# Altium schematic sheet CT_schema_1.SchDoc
size 540 x 499 mm
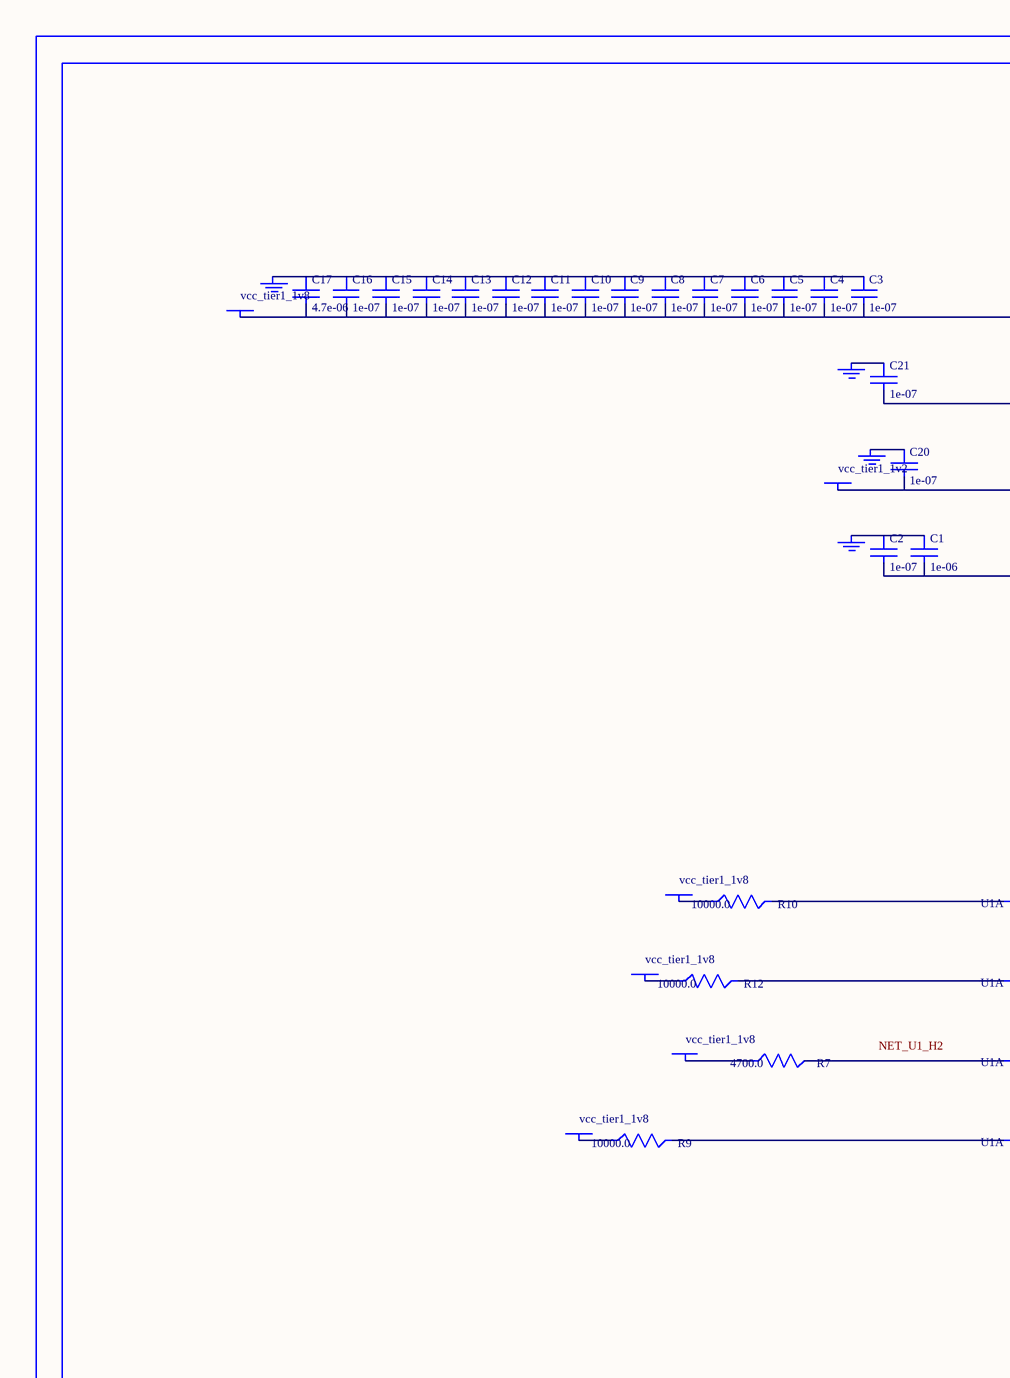
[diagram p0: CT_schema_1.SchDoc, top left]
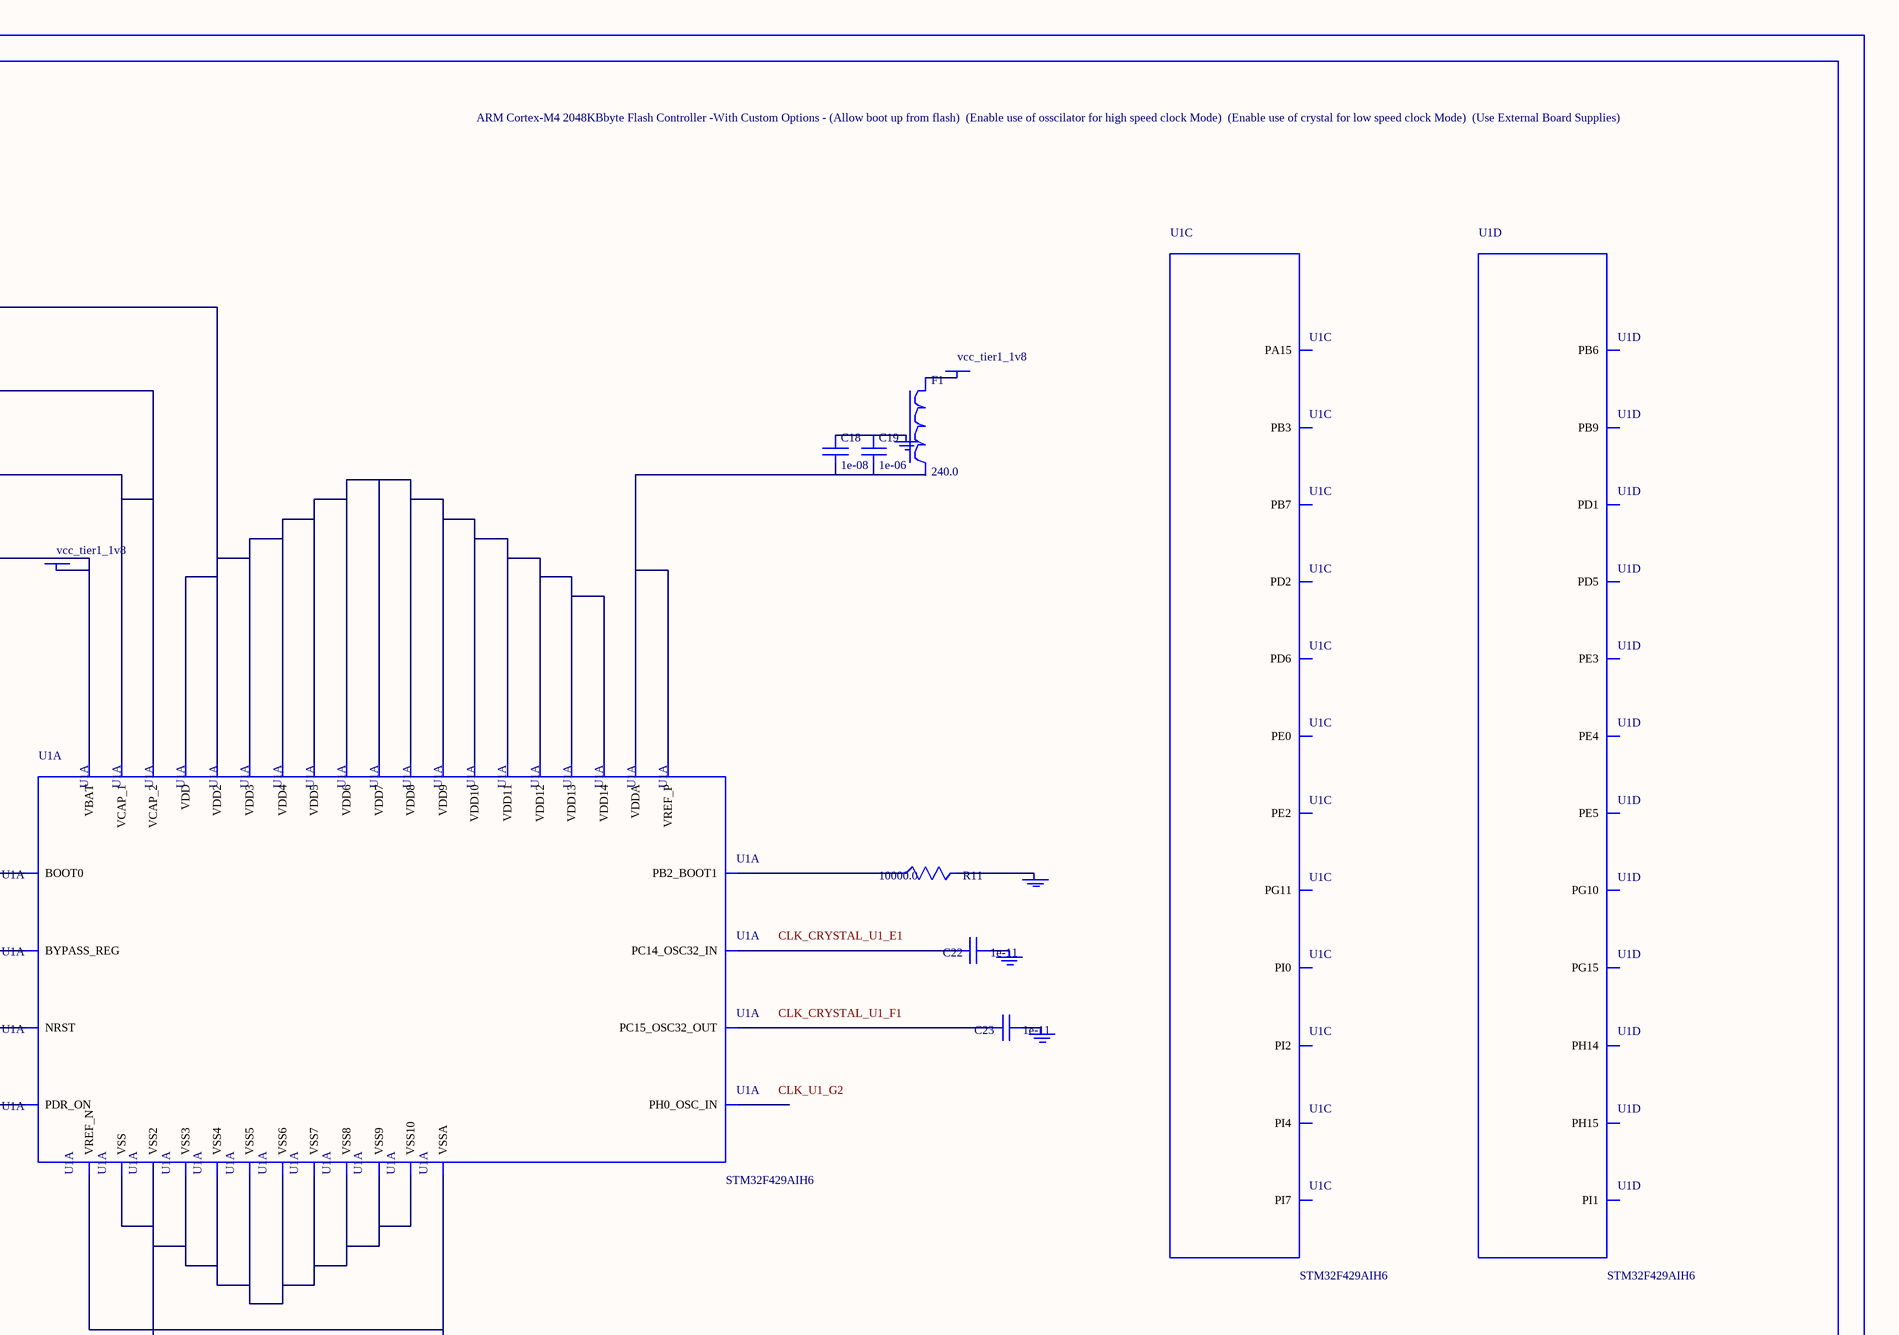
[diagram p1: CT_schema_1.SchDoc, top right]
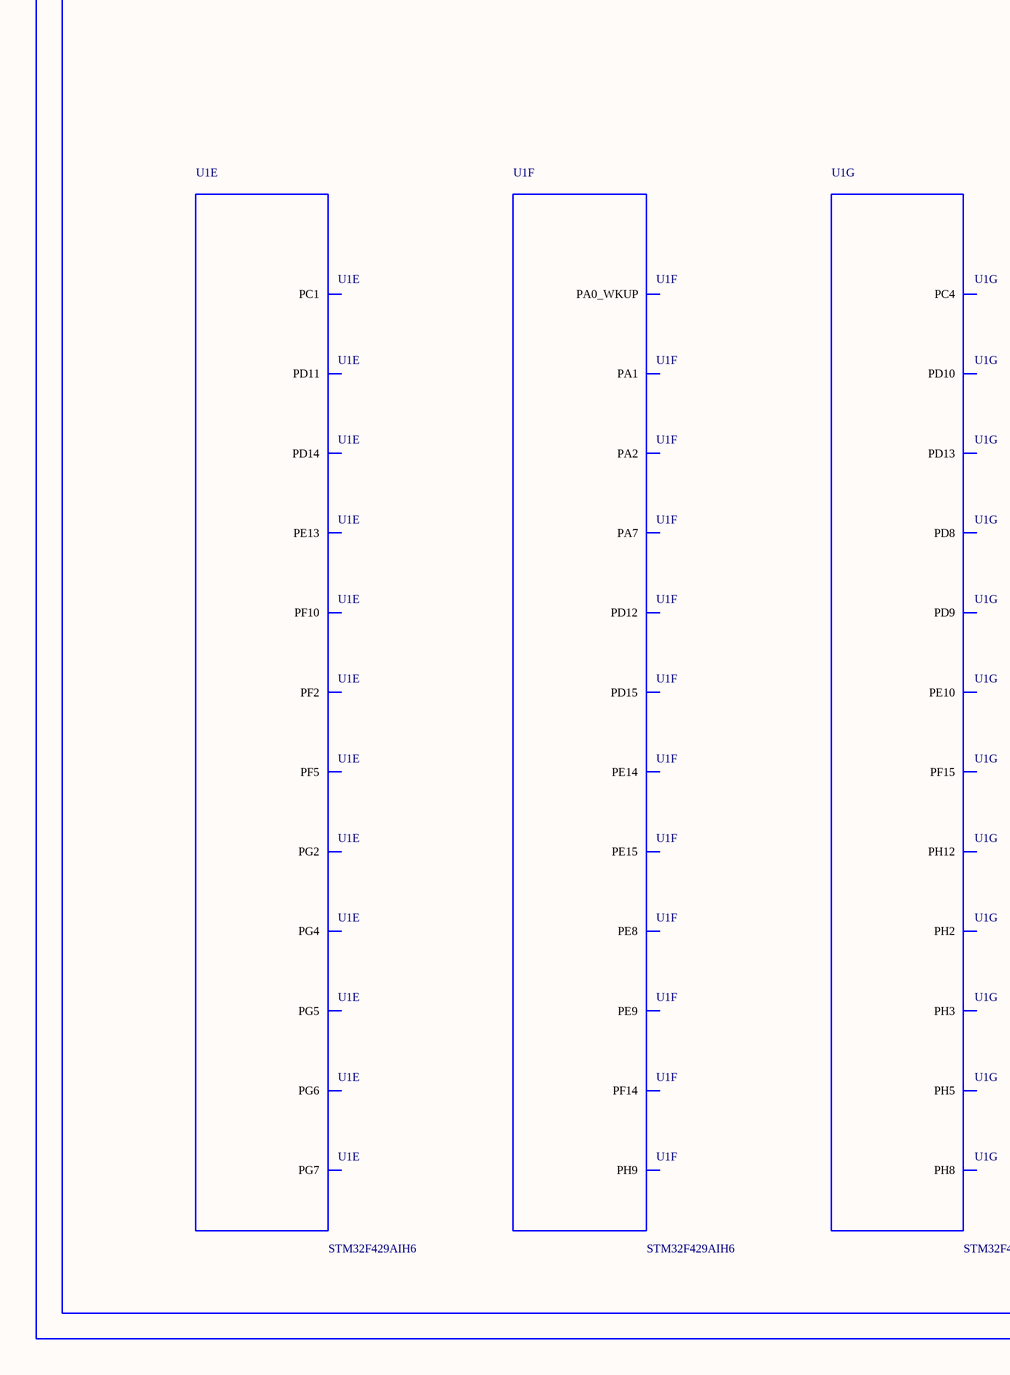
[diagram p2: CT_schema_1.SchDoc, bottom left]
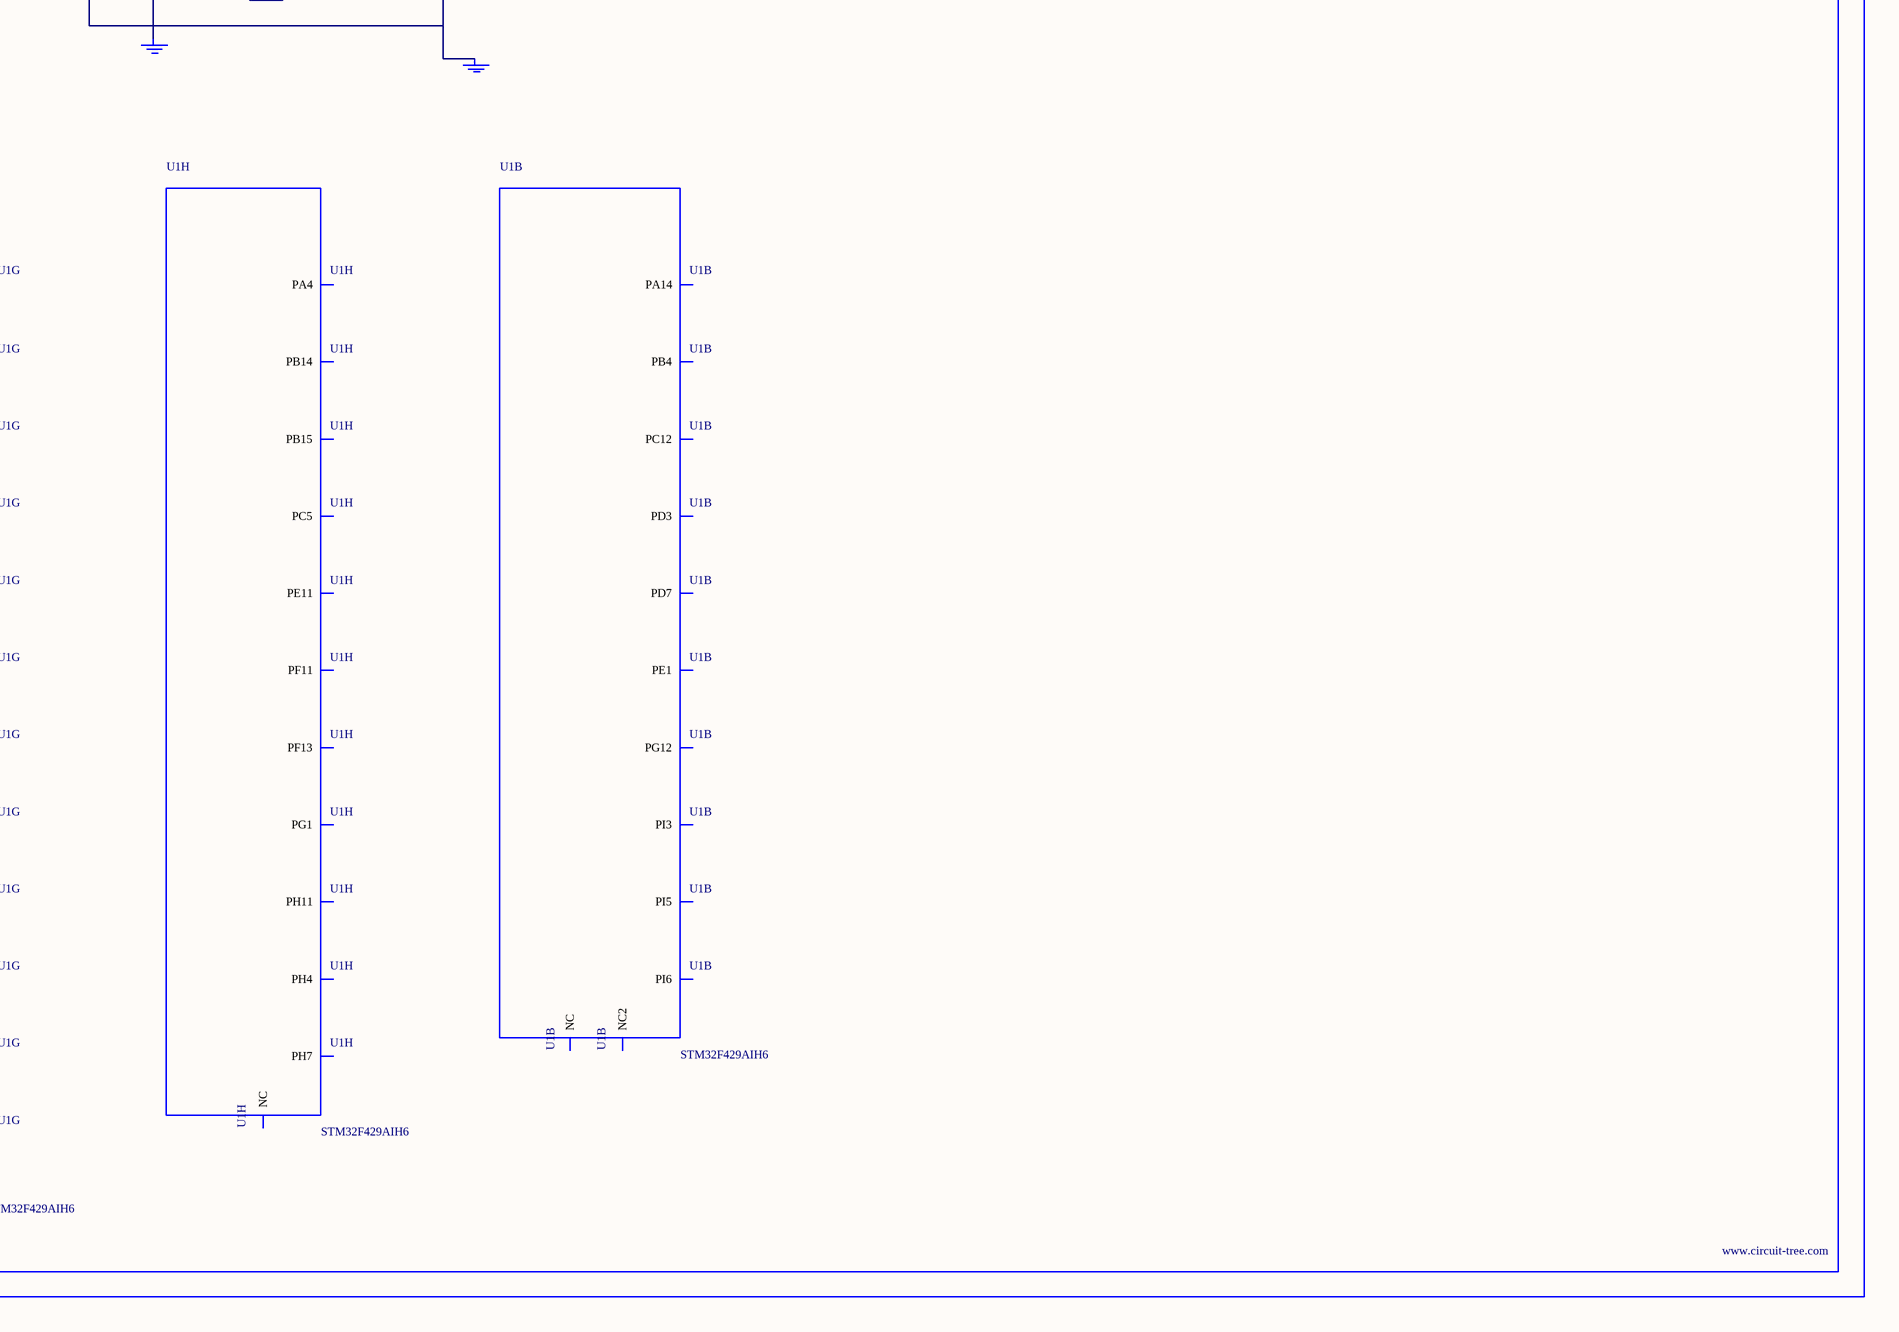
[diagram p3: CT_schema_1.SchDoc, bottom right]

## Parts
BORDER0  (no value)
C1  1e-06  [C0603]
C2  1e-07  [C0603]
C3  1e-07  [C0603]
C4  1e-07  [C0603]
C5  1e-07  [C0603]
C6  1e-07  [C0603]
C7  1e-07  [C0603]
C8  1e-07  [C0603]
C9  1e-07  [C0603]
C10  1e-07  [C0603]
C11  1e-07  [C0603]
C12  1e-07  [C0603]
C13  1e-07  [C0603]
C14  1e-07  [C0603]
C15  1e-07  [C0603]
C16  1e-07  [C0603]
C17  4.7e-06  [C0603]
C18  1e-08  [C0603]
C19  1e-06  [C0603]
C20  1e-07  [C0402]
C21  1e-07  [C0402]
C22  1e-11  [C0402]
C23  1e-11  [C0402]
F1  240.0  [L0603]
GND_INSTANCE_0_0  (no value)
GND_INSTANCE_0_1  (no value)
GND_INSTANCE_0_2  (no value)
GND_INSTANCE_0_3  (no value)
GND_INSTANCE_0_4  (no value)
GND_INSTANCE_0_5  (no value)
GND_INSTANCE_0_6  (no value)
GND_INSTANCE_0_7  (no value)
GND_INSTANCE_0_8  (no value)
GND_INSTANCE_0_9  (no value)
POWER_INSTANCE_0_0  vcc_tier1_1v8
POWER_INSTANCE_0_1  vcc_tier1_1v8
POWER_INSTANCE_0_2  vcc_tier1_1v8
POWER_INSTANCE_0_3  vcc_tier1_1v8
POWER_INSTANCE_0_4  vcc_tier1_1v8
POWER_INSTANCE_0_5  vcc_tier1_1v8
POWER_INSTANCE_0_6  vcc_tier1_1v2
POWER_INSTANCE_0_7  vcc_tier1_1v8
R7  4700.0  [R0603]
R9  10000.0  [R0603]
R10  10000.0  [R0603]
R11  10000.0  [R0603]
R12  10000.0  [R0603]
U1  STM32F429AIH6  [UFBGA169]  (parts A,B,C,D,E,F,G,H of 12)

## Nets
NetC1_1: C1.1 C2.1 GND_INSTANCE_0_0.0(GND)
NetC1_2: C1.2 C2.2 POWER_INSTANCE_0_0.0(PWR) U1.E5(VBAT)
NetC3_1: C3.1 C4.1 C5.1 C6.1 C7.1 C8.1 C9.1 C10.1 C11.1 C12.1 C13.1 C14.1 C15.1 C16.1 C17.1 GND_INSTANCE_0_2.0(GND)
NetC3_2: C3.2 C4.2 C5.2 C6.2 C7.2 C8.2 C9.2 C10.2 C11.2 C12.2 C13.2 C14.2 C15.2 C16.2 C17.2 POWER_INSTANCE_0_2.0(PWR) U1.D3(VDD2) U1.D6(VDD3) U1.D10(VDD) U1.E6(VDD4) U1.F4(VDD5) U1.F7(VDD6) U1.F8(VDD7) U1.G8(VDD9) U1.G10(VDD8) U1.H4(VDD10) U1.H8(VDD11) U1.J11(VDD12) U1.K6(VDD13) U1.L6(VDD14)
NetC18_1: C18.1 C19.1 GND_INSTANCE_0_1.0(GND)
NetC18_2: C18.2 C19.2 U1.J3(VREF_P) U1.J4(VDDA)
NetC20_1: C20.1 GND_INSTANCE_0_4.0(GND)
NetC20_2: C20.2 C21.2 POWER_INSTANCE_0_6.0(PWR) U1.D12(VCAP_2) U1.N9(VCAP_1)
NetC21_1: C21.1 GND_INSTANCE_0_5.0(GND)
NetC22_1: C22.1 GND_INSTANCE_0_6.0(GND)
NetC22_2: C22.2 U1.E1(PC14_OSC32_IN)
NetC23_1: C23.1 GND_INSTANCE_0_7.0(GND)
NetC23_2: C23.2 U1.F1(PC15_OSC32_OUT)
NetF1_1: F1.1 POWER_INSTANCE_0_1.0(PWR)
NetGND_INSTANCE_0_3_0: GND_INSTANCE_0_3.0(GND) R11.2
NetGND_INSTANCE_0_8_0: GND_INSTANCE_0_8.0(GND) U1.J1(VSSA) U1.J2(VREF_N)
NetGND_INSTANCE_0_9_0: GND_INSTANCE_0_9.0(GND) U1.D7(VSS2) U1.D11(VSS) U1.E7(VSS3) U1.F5(VSS4) U1.F6(VSS5) U1.G7(VSS6) U1.G9(VSS7) U1.J6(VSS9) U1.J7(VSS10) U1.J10(VSS8)
NetPOWER_INSTANCE_0_3_0: POWER_INSTANCE_0_3.0(PWR) R9.1
NetPOWER_INSTANCE_0_4_0: POWER_INSTANCE_0_4.0(PWR) R10.1
NetPOWER_INSTANCE_0_5_0: POWER_INSTANCE_0_5.0(PWR) R12.1
NetPOWER_INSTANCE_0_7_0: POWER_INSTANCE_0_7.0(PWR) R7.1
NetR7_2: R7.2 U1.H2(NRST)
NetR9_2: R9.2 U1.C3(PDR_ON)
NetR10_2: R10.2 U1.A5(BOOT0)
NetR11_1: R11.1 U1.L5(PB2_BOOT1)
NetR12_2: R12.2 U1.M1(BYPASS_REG)

Not connected (* = marked no-connect by the designer): F1 2; U1 A1(NC) A2(PI6) A3(PI5) A4(PE1) A6(PB4) A7(PG12) A8(PD7) A9(PD3) A10(PC12) A11(PA14) A12(PI3) A13(NC2) B1(PI7) B2(PE2) B3(PI4) B4(PE0) B5(PB7) B6(PB3) B7(PG11) B8(PD6) B9(PD2) B11(PA15) B12(PI2) B13(PI0) C1(PE3) C2(PE4) C4(PB9) C5(PB6) C6(PG15) C7(PG10) C8(PD5) C9(PD1) C11(PI1) C12(PH15) C13(PH14) D1(PE5) G2(PH0_OSC_IN) G5(PF2) G11(PG6) G12(PG7) G13(PG5) H1(PF10) H3(PF5) H5(PC1) H9(PE13) H10(PD11) H11(PD14) H12(PG4) H13(PG2) J5(PA0_WKUP) J8(PE8) J9(PE14) J12(PD15) J13(PD12) K1(PA1) K2(PA2) K4(PA7) K7(PF14) K8(PE9) K9(PE15) K10(PH9) K11(PD10) K12(PD13) K13(PD9) L1(PH3) L2(PH2) L3(PH5) L4(PC4) L7(PF15) L8(PE10) L10(PH8) L11(PH12) L12(PD8) L13(PB15) M2(PH4) M4(PC5) M5(PF11) M6(PF13) M7(PG1) M8(PE11) M10(PH7) M11(PH11) M13(PB14) N1(NC) N2(PA4)

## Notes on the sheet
- Labels drawn without touching a wire or pin: CLK_CRYSTAL_U1_E1, CLK_CRYSTAL_U1_F1, CLK_U1_G2, NET_U1_H2

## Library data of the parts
BORDER0 = BORDER_PAGE0
C1 C19 = C0603C105K3RACTU
C2-C16 = 06035C104K4Z2A
C17 = GRM188R6YA475KE15D
C18 = 06035C103K4Z2A
C20 C21 = C0402C104K3RACTU
C22 C23 = C0402C100K3GACTU
F1 = Z0603C241ASMST
GND_INSTANCE_0_0-GND_INSTANCE_0_9 = GND
POWER_INSTANCE_0_0-POWER_INSTANCE_0_7 = PWR
R7 = RC0603JR-074K7L
R9-R12 = RC0603JR-0710KL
